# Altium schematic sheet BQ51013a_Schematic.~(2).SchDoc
size A
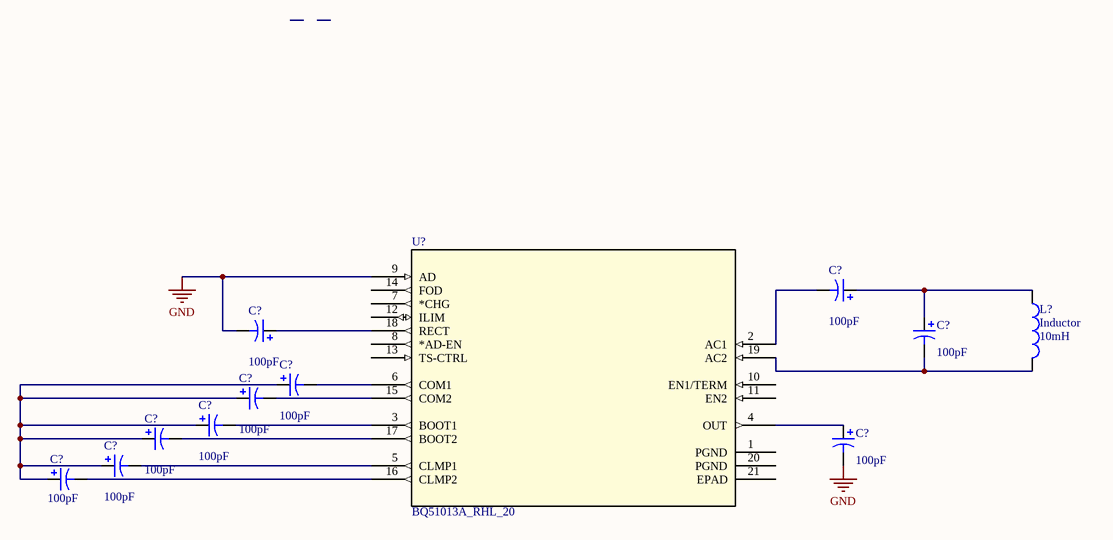
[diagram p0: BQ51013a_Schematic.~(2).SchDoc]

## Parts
(Parts that share a designator on the sheet are numbered #1, #2 ... from top to bottom, then left to right.)
C?#1  value 100pF  [C0805]
C?#2  value 100pF  [C0805]
C?#3  value 100pF  [C0805]
C?#4  value 100pF  [C0805]
C?#5  value 100pF  [C0805]
C?#6  value 100pF  [C0805]
C?#7  value 100pF  [C0805]
C?#8  value 100pF  [C0805]
C?#9  value 100pF  [C0805]
C?#10  value 100pF  [C0805]
L?  Inductor  value 10mH  [INDC1608L]
U?  BQ51013A_RHL_20  [RHL20_2P05X3P05]

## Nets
GND: C?#3.2 C?#8.2 U?.9(AD)
NetC?#1_1: C?#1.1 C?#2.1 L?.1
NetC?#1_2: C?#1.2 U?.2(AC1)
NetC?#2_2: C?#2.2 L?.2 U?.19(AC2)
NetC?#3_1: C?#3.1 U?.18(RECT)
NetC?#4_1: C?#4.1 C?#5.1 C?#6.1 C?#7.1 C?#9.1 C?#10.1
NetC?#4_2: C?#4.2 U?.6(COM1)
NetC?#5_2: C?#5.2 U?.15(COM2)
NetC?#6_2: C?#6.2 U?.3(BOOT1)
NetC?#7_2: C?#7.2 U?.17(BOOT2)
NetC?#8_1: C?#8.1 U?.4(OUT)
NetC?#9_2: C?#9.2 U?.5(CLMP1)
NetC?#10_2: C?#10.2 U?.16(CLMP2)

Not connected (* = marked no-connect by the designer): U? 1(PGND) 7(*CHG) 8(*AD-EN) 10(EN1/TERM) 11(EN2) 12(ILIM) 13(TS-CTRL) 14(FOD) 20(PGND) 21(EPAD)

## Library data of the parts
C?#1-C?#10 = Cap Pol3: Polarized Capacitor (Surface Mount)
L? = Inductor: Code_IEC: 1005
U? = BQ51013A_RHL_20: Imported; Vendor: TEXAS INSTRUMENTS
